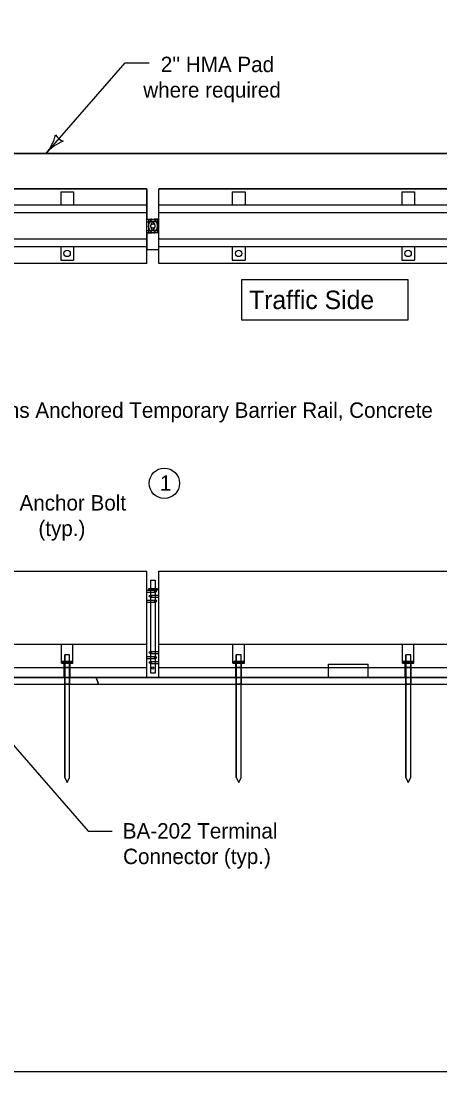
# Model space of a CAD drawing. Extents: x 10028 to 81668, y 3581 to 11018.
# Drawn here: x 18137 to 18550, y 7924 to 8962 of the extents above; entities that cross this region are included whole.
import ezdxf

# ---------------------------------------------------------------- set-up
doc = ezdxf.new("R2010")
doc.units = 0
for name, color, linetype in [('conPaving', 7, 'Continuous'), ('dsnCellsNorthArrow', 7, 'Continuous'), ('dsnTextTabulation', 7, 'Continuous'), ('Level 41', 7, 'Continuous'), ('Level 9', 7, 'Continuous'), ('SheetBorder', 7, 'Continuous')]:
    doc.layers.add(name, color=color, linetype=linetype)

msp = doc.modelspace()

# ---------------------------------------------------------------- linework, layer by layer
at = {"layer": 'conPaving'}
for p, q in [((18179.5, 8313.6), (18093.9, 8313.6)), ((18179.9, 8313.6), (18179.5, 8313.6)), ((18179.9, 8307.1), (18179.9, 8313.6)), ((18184.8, 8313.6), (18184.8, 8307.1)), ((18260.7, 8313.6), (18211, 8313.6)), ((18211, 8313.6), (18213.4, 8307.1)), ((18213.4, 8307.1), (18211, 8313.6)), ((18273.1, 8313.6), (18260.7, 8313.6)), ((18348.7, 8313.6), (18273.1, 8313.6)), ((18349.1, 8313.6), (18348.7, 8313.6)), ((18349.1, 8307.1), (18349.1, 8313.6)), ((18354, 8313.6), (18354, 8307.1)), ((18479.3, 8313.6), (18440, 8313.6)), ((18516.2, 8307.1), (18516.2, 8313.6)), ((18521.1, 8313.6), (18521.1, 8307.1)), ((18017.7, 8307.1), (18179.9, 8307.1)), ((18184.8, 8307.1), (18213.4, 8307.1)), ((18213.4, 8307.1), (18349.1, 8307.1)), ((18354, 8307.1), (18516.2, 8307.1)), ((18521.1, 8307.1), (18683.3, 8307.1))]:
    msp.add_line(p, q, dxfattribs=at)
for points in [[(18211, 8313.6), (18185.2, 8313.6), (18184.8, 8313.6)], [(18440, 8313.6), (18354.3, 8313.6), (18354, 8313.6)], [(18516.2, 8313.6), (18515.8, 8313.6), (18479.3, 8313.6)], [(18682.9, 8313.6), (18597.3, 8313.6), (18557.9, 8313.6), (18521.5, 8313.6), (18521.1, 8313.6)]]:
    msp.add_lwpolyline(points, dxfattribs=at)
at = {"layer": 'dsnTextTabulation'}
for p, q in [((18161.7, 8831), (18239.6, 8920.4)), ((18239.6, 8920.4), (18263.2, 8920.4)), ((18261, 8796.1), (17769.5, 8796.1)), ((18261, 8722.4), (18261, 8796.1)), ((18764.4, 8796.1), (18272.9, 8796.1)), ((18272.9, 8722.4), (18272.9, 8796.1)), ((18261, 8779.8), (17769.5, 8779.8)), ((18764.4, 8779.8), (18272.9, 8779.8)), ((18261, 8772.4), (17769.5, 8772.4)), ((18764.4, 8772.4), (18272.9, 8772.4)), ((18261, 8746.2), (17769.5, 8746.2)), ((18261, 8738.8), (17769.5, 8738.8)), ((18764.4, 8746.2), (18272.9, 8746.2)), ((18764.4, 8738.8), (18272.9, 8738.8)), ((18261, 8722.4), (17769.5, 8722.4)), ((18764.4, 8722.4), (18272.9, 8722.4)), ((17769.5, 8418.5), (18261, 8418.5)), ((18261, 8313.9), (18261, 8418.5)), ((18272.9, 8313.9), (18272.9, 8418.5)), ((18272.9, 8418.5), (18764.4, 8418.5)), ((17769.5, 8346.4), (18261, 8346.4)), ((18039, 8350.1), (18203.2, 8161.8)), ((18272.9, 8346.4), (18764.4, 8346.4)), ((17769.5, 8323.4), (18261, 8323.4)), ((18272.9, 8323.4), (18764.4, 8323.4)), ((18440, 8326.7), (18479.3, 8326.7)), ((18440, 8313.6), (18440, 8323.4)), ((18479.3, 8313.6), (18479.3, 8323.4)), ((18093.9, 8313.6), (18260.7, 8313.6)), ((18273.1, 8313.6), (18440, 8313.6)), ((18479.3, 8313.6), (18557.9, 8313.6)), ((18203.2, 8161.8), (18226.8, 8161.8))]:
    msp.add_line(p, q, dxfattribs=at)
msp.add_circle((18278.2, 8505.3), 15, dxfattribs=at)
for centre, radius, start, end in [((18129.3, 8858.6), 42.5, 319.5664, 347.6389), ((18194, 8803.5), 42.5, 111.4939, 139.5664), ((18184.8, 8858.1), 16.4, 211.833, 247.2997)]:
    msp.add_arc(centre, radius, start, end, dxfattribs=at)
at = {"layer": 'Level 41'}
for p, q in [((18176.1, 8793), (18176.1, 8779.8)), ((18176.1, 8793), (18188.6, 8793)), ((18188.6, 8793), (18188.6, 8779.8)), ((18345.2, 8793), (18357.8, 8793)), ((18345.2, 8793), (18345.2, 8779.8)), ((18357.8, 8793), (18357.8, 8779.8)), ((18512.3, 8793), (18524.9, 8793)), ((18512.3, 8793), (18512.3, 8779.8)), ((18524.9, 8793), (18524.9, 8779.8)), ((18261, 8766), (18264.9, 8766)), ((18261, 8763.6), (18264.9, 8763.6)), ((18272.9, 8766), (18268.9, 8766)), ((18272.9, 8763.6), (18268.9, 8763.6)), ((18261, 8755), (18264.9, 8755)), ((18261, 8752.6), (18264.9, 8752.6)), ((18272.9, 8755), (18268.9, 8755)), ((18272.9, 8752.6), (18268.9, 8752.6)), ((18176.1, 8738.8), (18176.1, 8725.5)), ((18188.6, 8738.8), (18188.6, 8725.5)), ((18345.2, 8738.8), (18345.2, 8725.5)), ((18357.8, 8738.8), (18357.8, 8725.5)), ((18512.3, 8738.8), (18512.3, 8725.5)), ((18524.9, 8738.8), (18524.9, 8725.5)), ((18176.1, 8725.5), (18188.6, 8725.5)), ((18345.2, 8725.5), (18357.8, 8725.5)), ((18512.3, 8725.5), (18524.9, 8725.5)), ((18261, 8399.9), (18269.5, 8399.9)), ((18261, 8397.7), (18269.5, 8397.7)), ((18261, 8390), (18269.5, 8390)), ((18261, 8387.9), (18269.5, 8387.9)), ((18264.4, 8394.9), (18272.9, 8394.9)), ((18264.4, 8392.8), (18272.9, 8392.8)), ((18176.7, 8327.8), (18176.7, 8346.4)), ((18188, 8327.8), (18188, 8346.4)), ((18345.8, 8327.8), (18345.8, 8346.4)), ((18357.2, 8327.8), (18357.2, 8346.4)), ((18513, 8327.8), (18513, 8346.4)), ((18524.3, 8327.8), (18524.3, 8346.4)), ((18261, 8334.3), (18269.5, 8334.3)), ((18264.4, 8339.2), (18272.9, 8339.2)), ((18264.4, 8337.1), (18272.9, 8337.1)), ((18176.7, 8327.8), (18188, 8327.8)), ((18179.5, 8313.6), (18179.5, 8327.8)), ((18185.2, 8313.6), (18185.2, 8327.8)), ((18261, 8332.2), (18269.5, 8332.2)), ((18264.4, 8329.4), (18272.9, 8329.4)), ((18264.4, 8327.3), (18272.9, 8327.3)), ((18345.8, 8327.8), (18357.2, 8327.8)), ((18348.7, 8313.6), (18348.7, 8327.8)), ((18354.3, 8313.6), (18354.3, 8327.8)), ((18513, 8327.8), (18524.3, 8327.8)), ((18515.8, 8313.6), (18515.8, 8327.8)), ((18521.5, 8313.6), (18521.5, 8327.8))]:
    msp.add_line(p, q, dxfattribs=at)
for centre, radius in [((18182.3, 8732.2), 3.15), ((18351.5, 8732.2), 3.15), ((18518.6, 8732.2), 3.15), ((18269.5, 8398.8), 1.06), ((18264.4, 8393.9), 1.06), ((18269.5, 8389), 1.06), ((18264.4, 8338.2), 1.06), ((18269.5, 8333.3), 1.06), ((18264.4, 8328.4), 1.06)]:
    msp.add_circle(centre, radius, dxfattribs=at)
for centre, radius, start, end in [((18268.9, 8759.3), 6.68, 90, 270), ((18268.9, 8759.3), 4.33, 90, 270), ((18264.9, 8759.3), 6.68, 270, 90), ((18264.9, 8759.3), 4.33, 270, 90)]:
    msp.add_arc(centre, radius, start, end, dxfattribs=at)
at = {"layer": 'Level 9'}
for p, q in [((17757.6, 8831), (19777.1, 8831)), ((18258, 8831), (17848, 8831)), ((17848, 8796.1), (18261, 8796.1)), ((18261, 8766), (18264.9, 8766)), ((18262.8, 8765.8), (18271, 8765.8)), ((18262.8, 8752.7), (18262.8, 8765.8)), ((18266.4, 8765.8), (18267.5, 8765.8)), ((18268.9, 8766), (18272.9, 8766)), ((18271, 8765.8), (18271, 8752.7)), ((18264.9, 8752.6), (18261, 8752.6)), ((18271, 8752.7), (18262.8, 8752.7)), ((18267.7, 8752.7), (18266.1, 8752.7)), ((18272.9, 8752.6), (18268.9, 8752.6)), ((18261, 8736), (18272.9, 8736)), ((18261, 8736), (18272.9, 8736)), ((18264.9, 8409.7), (18269, 8409.7)), ((18264.9, 8401.5), (18264.9, 8409.7)), ((18269, 8409.7), (18269, 8401.5)), ((18262.8, 8401.5), (18271, 8401.5)), ((18262.8, 8399.9), (18262.8, 8401.5)), ((18271, 8399.9), (18262.8, 8399.9)), ((18264.9, 8317.9), (18264.9, 8399.9)), ((18269, 8399.9), (18269, 8317.9)), ((18271, 8401.5), (18271, 8399.9)), ((18184.8, 8336), (18179.9, 8336)), ((18179.9, 8336), (18179.9, 8329.4)), ((18184.8, 8336), (18179.9, 8336)), ((18179.9, 8214.8), (18179.9, 8336)), ((18184.8, 8329.4), (18184.8, 8336)), ((18184.8, 8214.8), (18184.8, 8336)), ((18354, 8336), (18349.1, 8336)), ((18349.1, 8336), (18349.1, 8329.4)), ((18354, 8336), (18349.1, 8336)), ((18349.1, 8214.8), (18349.1, 8336)), ((18354, 8329.4), (18354, 8336)), ((18354, 8214.8), (18354, 8336)), ((18521.1, 8336), (18516.2, 8336)), ((18516.2, 8336), (18516.2, 8329.4)), ((18521.1, 8336), (18516.2, 8336)), ((18516.2, 8214.8), (18516.2, 8336)), ((18521.1, 8329.4), (18521.1, 8336)), ((18521.1, 8214.8), (18521.1, 8336)), ((18177.4, 8329.4), (18177.4, 8327.8)), ((18179.9, 8329.4), (18177.4, 8329.4)), ((18177.4, 8327.8), (18177.4, 8329.4)), ((18177.4, 8327.8), (18179.5, 8327.8)), ((18179.5, 8327.8), (18179.9, 8327.8)), ((18184.8, 8329.4), (18179.9, 8329.4)), ((18179.9, 8329.4), (18179.9, 8327.8)), ((18179.9, 8327.8), (18179.9, 8329.4)), ((18179.9, 8329.4), (18184.8, 8329.4)), ((18184.8, 8327.8), (18179.9, 8327.8)), ((18179.9, 8327.8), (18179.9, 8323.4)), ((18179.9, 8327.8), (18184.8, 8327.8)), ((18184.8, 8323.4), (18179.9, 8323.4)), ((18179.9, 8323.4), (18179.9, 8313.6)), ((18179.9, 8323.4), (18184.8, 8323.4)), ((18184.8, 8327.8), (18184.8, 8329.4)), ((18184.8, 8329.4), (18184.8, 8327.8)), ((18184.8, 8323.4), (18184.8, 8327.8)), ((18184.8, 8313.6), (18184.8, 8323.4)), ((18346.6, 8329.4), (18346.6, 8327.8)), ((18349.1, 8329.4), (18346.6, 8329.4)), ((18346.6, 8327.8), (18346.6, 8329.4)), ((18346.6, 8327.8), (18348.7, 8327.8)), ((18348.7, 8327.8), (18349.1, 8327.8)), ((18354, 8329.4), (18349.1, 8329.4)), ((18349.1, 8329.4), (18349.1, 8327.8)), ((18349.1, 8327.8), (18349.1, 8329.4)), ((18349.1, 8329.4), (18354, 8329.4)), ((18354, 8327.8), (18349.1, 8327.8)), ((18349.1, 8327.8), (18349.1, 8323.4)), ((18349.1, 8327.8), (18354, 8327.8)), ((18354, 8323.4), (18349.1, 8323.4)), ((18349.1, 8323.4), (18349.1, 8313.6)), ((18349.1, 8323.4), (18354, 8323.4)), ((18354, 8327.8), (18354, 8329.4)), ((18354, 8329.4), (18354, 8327.8)), ((18354, 8323.4), (18354, 8327.8)), ((18354, 8313.6), (18354, 8323.4)), ((18440, 8323.4), (18440, 8326.7)), ((18440, 8323.4), (18479.3, 8323.4)), ((18479.3, 8323.4), (18479.3, 8326.7)), ((18513.7, 8329.4), (18513.7, 8327.8)), ((18516.2, 8329.4), (18513.7, 8329.4)), ((18513.7, 8327.8), (18513.7, 8329.4)), ((18513.7, 8327.8), (18515.8, 8327.8)), ((18515.8, 8327.8), (18516.2, 8327.8)), ((18521.1, 8329.4), (18516.2, 8329.4)), ((18516.2, 8329.4), (18516.2, 8327.8)), ((18516.2, 8327.8), (18516.2, 8329.4)), ((18516.2, 8329.4), (18521.1, 8329.4)), ((18521.1, 8327.8), (18516.2, 8327.8)), ((18516.2, 8327.8), (18516.2, 8323.4)), ((18516.2, 8327.8), (18521.1, 8327.8)), ((18521.1, 8323.4), (18516.2, 8323.4)), ((18516.2, 8323.4), (18516.2, 8313.6)), ((18516.2, 8323.4), (18521.1, 8323.4)), ((18521.1, 8327.8), (18521.1, 8329.4)), ((18521.1, 8329.4), (18521.1, 8327.8)), ((18521.1, 8323.4), (18521.1, 8327.8)), ((18521.1, 8313.6), (18521.1, 8323.4)), ((17462, 8313.6), (20253.1, 8313.6)), ((18184.8, 8313.6), (18179.9, 8313.6)), ((18179.9, 8313.6), (18179.9, 8307.1)), ((18179.9, 8313.6), (18184.8, 8313.6)), ((18184.8, 8307.1), (18184.8, 8313.6)), ((18260.7, 8313.6), (18261, 8313.9)), ((18269, 8317.9), (18264.9, 8317.9)), ((18272.9, 8313.9), (18273.1, 8313.6)), ((18354, 8313.6), (18349.1, 8313.6)), ((18349.1, 8313.6), (18349.1, 8307.1)), ((18349.1, 8313.6), (18354, 8313.6)), ((18354, 8307.1), (18354, 8313.6)), ((18521.1, 8313.6), (18516.2, 8313.6)), ((18516.2, 8313.6), (18516.2, 8307.1)), ((18516.2, 8313.6), (18521.1, 8313.6)), ((18521.1, 8307.1), (18521.1, 8313.6)), ((17757.6, 8307.1), (19777.1, 8307.1)), ((18184.8, 8307.1), (18179.9, 8307.1)), ((18179.9, 8307.1), (18179.9, 8214.8)), ((18179.9, 8307.1), (18184.8, 8307.1)), ((18184.8, 8214.8), (18184.8, 8307.1)), ((18354, 8307.1), (18349.1, 8307.1)), ((18349.1, 8307.1), (18349.1, 8214.8)), ((18349.1, 8307.1), (18354, 8307.1)), ((18354, 8214.8), (18354, 8307.1)), ((18521.1, 8307.1), (18516.2, 8307.1)), ((18516.2, 8307.1), (18516.2, 8214.8)), ((18516.2, 8307.1), (18521.1, 8307.1)), ((18521.1, 8214.8), (18521.1, 8307.1)), ((18179.9, 8214.8), (18182.3, 8209.8)), ((18179.9, 8214.8), (18182.3, 8209.8)), ((18182.3, 8209.8), (18184.8, 8214.8)), ((18182.3, 8209.8), (18184.8, 8214.8)), ((18349.1, 8214.8), (18351.5, 8209.8)), ((18349.1, 8214.8), (18351.5, 8209.8)), ((18351.5, 8209.8), (18354, 8214.8)), ((18351.5, 8209.8), (18354, 8214.8)), ((18516.2, 8214.8), (18518.6, 8209.8)), ((18516.2, 8214.8), (18518.6, 8209.8)), ((18518.6, 8209.8), (18521.1, 8214.8)), ((18518.6, 8209.8), (18521.1, 8214.8))]:
    msp.add_line(p, q, dxfattribs=at)
for points in [[(19777.1, 8831), (18443, 8831), (18258, 8831), (18258, 8831)], [(18258, 8831), (18258, 8831), (18258, 8831)], [(18261, 8796.1), (18261, 8779.8), (18261, 8772.4), (18261, 8766)], [(18272.9, 8766), (18272.9, 8772.4), (18272.9, 8779.8), (18272.9, 8796.1)], [(18272.9, 8796.1), (18443, 8796.1), (18764.4, 8796.1)], [(18261, 8752.6), (18261, 8746.2), (18261, 8738.8), (18261, 8736)], [(18272.9, 8736), (18272.9, 8738.8), (18272.9, 8746.2), (18272.9, 8752.6)], [(18177.4, 8329.4), (18187.3, 8329.4), (18187.3, 8327.8), (18177.4, 8327.8)], [(18187.3, 8327.8), (18187.3, 8329.4), (18184.8, 8329.4)], [(18184.8, 8327.8), (18185.2, 8327.8), (18187.3, 8327.8)], [(18346.6, 8329.4), (18356.4, 8329.4), (18356.4, 8327.8), (18346.6, 8327.8)], [(18356.4, 8327.8), (18356.4, 8329.4), (18354, 8329.4)], [(18354, 8327.8), (18354.3, 8327.8), (18356.4, 8327.8)], [(18513.7, 8329.4), (18523.5, 8329.4), (18523.5, 8327.8), (18513.7, 8327.8)], [(18523.5, 8327.8), (18523.5, 8329.4), (18521.1, 8329.4)], [(18521.1, 8327.8), (18521.5, 8327.8), (18523.5, 8327.8)]]:
    msp.add_lwpolyline(points, dxfattribs=at)
msp.add_lwpolyline([(18354.7, 8706.4), (18518.4, 8706.4), (18518.4, 8666.4), (18354.7, 8666.4)], close=True, dxfattribs=at)
for centre, radius in [((18266.9, 8759.3), 2.05), ((18266.9, 8322.9), 1.02)]:
    msp.add_circle(centre, radius, dxfattribs=at)
for centre, start, end in [((18264.9, 8759.3), 77.6043, 90), ((18268.9, 8759.3), 90, 102.3957), ((18264.9, 8759.3), 270, 280.2309), ((18268.9, 8759.3), 259.7691, 270)]:
    msp.add_arc(centre, 6.68, start, end, dxfattribs=at)
at = {"layer": 'SheetBorder'}
msp.add_lwpolyline([(17332.5, 9944), (20467.5, 9944), (20467.5, 7924), (17332.5, 7924)], close=True, dxfattribs=at)

# ---------------------------------------------------------------- texts
at = {"layer": 'dsnCellsNorthArrow'}
for s, height, p in [("2'' HMA Pad", 15.2, (18274.7, 8911.3)), ('where required', 15.2, (18257.4, 8886.1)), ('Traffic Side', 18.24, (18361.7, 8677.3)), ('4 Sections Anchored Temporary Barrier Rail, Concrete', 15.2, (18050.4, 8569.9)), ('Rail Anchor Bolt', 15.2, (18094.7, 8478.4)), ('(typ.)', 15.2, (18154, 8453.2)), ('BA-202 Terminal', 15.2, (18237.2, 8154.5)), ('Connector (typ.)', 15.2, (18237.5, 8129.3))]:
    msp.add_text(s, height=height, dxfattribs=at).set_placement(p)
at = {"layer": 'dsnTextTabulation'}
msp.add_text('1', height=15.2, dxfattribs=at).set_placement((18273.8, 8498))

doc.saveas('drawing.dxf')
